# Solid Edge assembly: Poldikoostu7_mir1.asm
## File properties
Author: Türk
Template: Iso Assembly.asm
Last saved by: Türk
Revision: 2
Application: Solid Edge
Username: Türk
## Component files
Polt220x20.par
Mutter.par
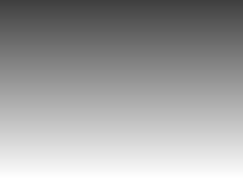
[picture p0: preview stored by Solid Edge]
